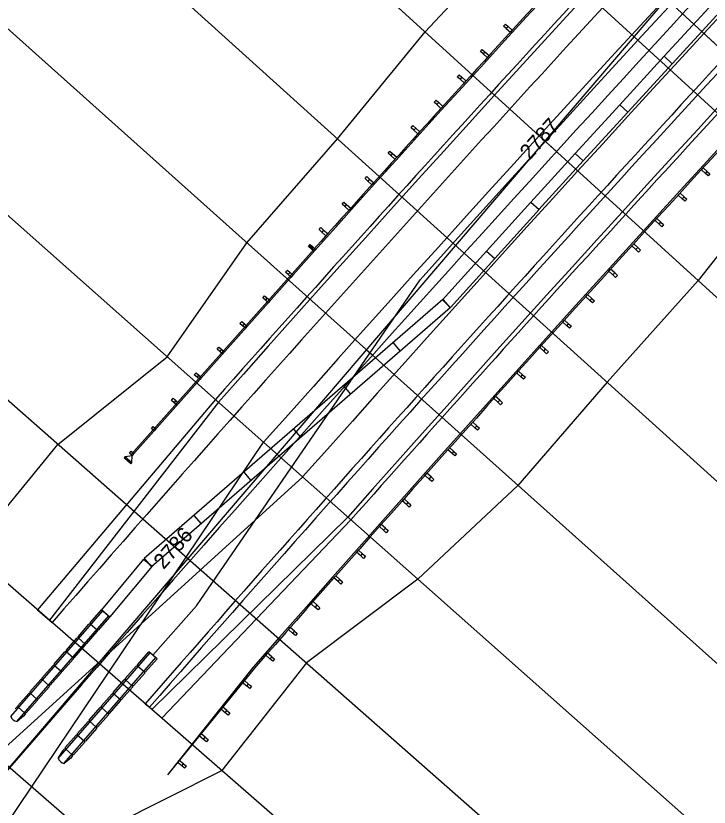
# Model space of a CAD drawing. Extents: x 2376379 to 2383101, y 559608 to 561720.
# Drawn here: x 2376840.8 to 2376967, y 561020.9 to 561165 of the extents above; entities that cross this region are included whole.
import ezdxf

# ---------------------------------------------------------------- set-up
doc = ezdxf.new("R2010")
doc.units = 0
for name, color, linetype in [('BR_X_SV_Bottom_of_Beam', 7, 'Continuous'), ('BR_X_SV_Deck_Top', 7, 'Continuous'), ('DR_X_Headwall', 7, 'Continuous'), ('DT_X_Contour_Minor', 7, 'Continuous'), ('PM_X_CL_Dashed', 7, 'Continuous'), ('PM_X_CL_Pass_Proh_Lt', 7, 'Continuous'), ('PM_X_Surveyed_Line', 7, 'Continuous'), ('PV_X_COP', 7, 'Continuous'), ('PV_X_EOP', 7, 'Continuous'), ('RD_X_Cells', 7, 'Continuous'), ('SV_X_Text', 7, 'Continuous')]:
    doc.layers.add(name, color=color, linetype=linetype)

msp = doc.modelspace()

# ---------------------------------------------------------------- linework, layer by layer
at = {"layer": 'BR_X_SV_Bottom_of_Beam'}
for p, q in [((2376966.95, 561166.42), (2376958.82, 561157.6)), ((2376968.42, 561165.07), (2376960.29, 561156.24)), ((2376958.82, 561157.6), (2376950.71, 561148.75)), ((2376958.82, 561157.6), (2376950.71, 561148.75)), ((2376958.82, 561157.6), (2376950.71, 561148.75)), ((2376958.82, 561157.6), (2376960.29, 561156.24)), ((2376958.82, 561157.6), (2376960.29, 561156.24)), ((2376958.82, 561157.6), (2376960.29, 561156.24)), ((2376958.82, 561157.6), (2376960.29, 561156.24)), ((2376960.29, 561156.24), (2376952.18, 561147.4)), ((2376960.29, 561156.24), (2376952.18, 561147.4)), ((2376960.29, 561156.24), (2376952.18, 561147.4)), ((2376950.71, 561148.75), (2376942.61, 561139.89)), ((2376950.71, 561148.75), (2376952.18, 561147.4)), ((2376950.71, 561148.75), (2376952.18, 561147.4)), ((2376950.71, 561148.75), (2376952.18, 561147.4)), ((2376950.71, 561148.75), (2376952.18, 561147.4)), ((2376952.18, 561147.4), (2376944.09, 561138.54)), ((2376942.61, 561139.89), (2376934.54, 561131.01)), ((2376942.61, 561139.89), (2376944.09, 561138.54)), ((2376942.61, 561139.89), (2376944.09, 561138.54)), ((2376944.09, 561138.54), (2376936.01, 561129.67)), ((2376934.53, 561131.01), (2376926.48, 561122.12)), ((2376934.53, 561131.01), (2376936.02, 561129.67)), ((2376934.54, 561131.01), (2376936.01, 561129.67)), ((2376936.02, 561129.67), (2376927.96, 561120.78)), ((2376926.48, 561122.12), (2376918.44, 561113.21)), ((2376926.48, 561122.12), (2376927.96, 561120.78)), ((2376926.48, 561122.12), (2376927.96, 561120.78)), ((2376927.96, 561120.78), (2376919.92, 561111.87)), ((2376918.52, 561113.29), (2376864.14, 561066.11)), ((2376918.44, 561113.21), (2376919.92, 561111.87)), ((2376918.52, 561113.29), (2376919.83, 561111.78)), ((2376919.83, 561111.78), (2376865.45, 561064.6)), ((2376909.46, 561105.43), (2376910.77, 561103.92)), ((2376900.4, 561097.57), (2376901.71, 561096.06)), ((2376891.33, 561089.7), (2376892.64, 561088.19)), ((2376882.27, 561081.84), (2376883.58, 561080.33)), ((2376781.2, 560979.35), (2376892.99, 561080.98)), ((2376873.2, 561073.98), (2376874.51, 561072.47)), ((2376901.22, 561073.68), (2376865.54, 561038.64)), ((2376864.02, 561066), (2376856.34, 561056.78)), ((2376864.02, 561066), (2376865.56, 561064.72)), ((2376864.14, 561066.11), (2376865.45, 561064.6)), ((2376865.56, 561064.72), (2376857.88, 561055.5)), ((2376854.28, 561054.41), (2376856.36, 561056.79)), ((2376856.34, 561056.78), (2376857.88, 561055.5)), ((2376857.87, 561055.48), (2376856.36, 561056.79)), ((2376839.88, 561037.35), (2376856.61, 561056.58)), ((2376857.61, 561055.7), (2376840.88, 561036.47)), ((2376855.79, 561053.09), (2376857.87, 561055.48)), ((2376852.09, 561051.89), (2376854.06, 561054.15)), ((2376854.29, 561054.17), (2376854.06, 561054.15)), ((2376854.28, 561054.41), (2376854.29, 561054.17)), ((2376855.55, 561053.08), (2376854.29, 561054.17)), ((2376853.6, 561050.58), (2376855.57, 561052.84)), ((2376855.79, 561053.09), (2376855.55, 561053.08)), ((2376855.55, 561053.08), (2376855.57, 561052.84)), ((2376849.9, 561049.38), (2376851.87, 561051.64)), ((2376852.11, 561051.66), (2376851.87, 561051.64)), ((2376852.09, 561051.89), (2376852.11, 561051.66)), ((2376853.36, 561050.56), (2376852.11, 561051.66)), ((2376851.41, 561048.06), (2376853.38, 561050.33)), ((2376853.6, 561050.58), (2376853.36, 561050.56)), ((2376853.36, 561050.56), (2376853.38, 561050.33)), ((2376847.71, 561046.86), (2376849.68, 561049.13)), ((2376849.92, 561049.14), (2376849.68, 561049.13)), ((2376849.9, 561049.38), (2376849.92, 561049.14)), ((2376851.18, 561048.05), (2376849.92, 561049.14)), ((2376851.41, 561048.06), (2376851.18, 561048.05)), ((2376851.18, 561048.05), (2376851.19, 561047.81)), ((2376845.52, 561044.35), (2376847.49, 561046.61)), ((2376847.73, 561046.63), (2376847.49, 561046.61)), ((2376847.71, 561046.86), (2376847.73, 561046.63)), ((2376848.99, 561045.53), (2376847.73, 561046.63)), ((2376849.22, 561045.55), (2376851.19, 561047.81)), ((2376847.03, 561043.04), (2376849, 561045.3)), ((2376849.22, 561045.55), (2376848.99, 561045.53)), ((2376848.99, 561045.53), (2376849, 561045.3)), ((2376843.34, 561041.83), (2376845.31, 561044.1)), ((2376845.54, 561044.11), (2376845.31, 561044.1)), ((2376845.52, 561044.35), (2376845.54, 561044.11)), ((2376846.8, 561043.02), (2376845.54, 561044.11)), ((2376846.81, 561042.78), (2376844.85, 561040.52)), ((2376847.03, 561043.04), (2376846.8, 561043.02)), ((2376846.8, 561043.02), (2376846.81, 561042.78)), ((2376841.15, 561039.32), (2376843.12, 561041.58)), ((2376843.35, 561041.6), (2376843.12, 561041.58)), ((2376843.34, 561041.83), (2376843.35, 561041.6)), ((2376844.61, 561040.5), (2376843.35, 561041.6)), ((2376844.63, 561040.27), (2376842.66, 561038.01)), ((2376844.85, 561040.52), (2376844.61, 561040.5)), ((2376844.61, 561040.5), (2376844.63, 561040.27)), ((2376840.64, 561038.74), (2376840.93, 561039.07)), ((2376841.16, 561039.08), (2376840.93, 561039.07)), ((2376841.15, 561039.32), (2376841.16, 561039.08)), ((2376842.42, 561037.99), (2376841.16, 561039.08)), ((2376842.66, 561038.01), (2376842.42, 561037.99)), ((2376842.42, 561037.99), (2376842.44, 561037.76)), ((2376842.15, 561037.43), (2376840.98, 561036.46)), ((2376842.44, 561037.76), (2376842.15, 561037.43))]:
    msp.add_line(p, q, dxfattribs=at)
for centre, radius, start, end in [((2381174.86, 557281.31), 5724.68, 134.05646, 138.41459), ((2381174.86, 557281.31), 5713.68, 134.05646, 138.41459), ((2376841.14, 561037.78), 1.34, 194.7908, 263.1422)]:
    msp.add_arc(centre, radius, start, end, dxfattribs=at)
at = {"layer": 'BR_X_SV_Deck_Top'}
for p, q in [((2376877.09, 561095.09), (2376844.73, 561056.78)), ((2376844.73, 561056.78), (2376847.37, 561054.48))]:
    msp.add_line(p, q, dxfattribs=at)
for radius, start, end in [(5745.93, 136.826935, 138.414594), (5741.43, 136.827718, 138.914563)]:
    msp.add_arc((2381174.86, 557281.31), radius, start, end, dxfattribs=at)
at = {"layer": 'DR_X_Headwall'}
for p, q in [((2376867.34, 561037.07), (2376901.78, 561073.18)), ((2376865.08, 561039.04), (2376867.34, 561037.07))]:
    msp.add_line(p, q, dxfattribs=at)
msp.add_arc((2381174.86, 557281.31), 5712.93, 137.07842, 138.41459, dxfattribs=at)
at = {"layer": 'DT_X_Contour_Minor'}
msp.add_line((2376855.78, 561016.25), (2376878.27, 561027.54), dxfattribs=at)
for points in [[(2376832.49, 561067.46), (2376848.42, 561086.92), (2376868.33, 561102.87), (2376882.82, 561123.61), (2376899.35, 561142.55), (2376915.28, 561162.04), (2376932.44, 561180.41), (2376951.72, 561196.82), (2376966, 561252.44)], [(2376980.42, 561136.31), (2376965.01, 561116.73), (2376948.44, 561098.22), (2376932.15, 561079.45), (2376913.93, 561062.4), (2376893.67, 561047.12), (2376878.27, 561027.54)]]:
    msp.add_lwpolyline(points, dxfattribs=at)
at = {"layer": 'PM_X_CL_Dashed'}
for p, q in [((2376965.58, 561136.92), (2376965.92, 561137.29)), ((2376966.32, 561136.25), (2376965.58, 561136.92)), ((2376966.66, 561136.61), (2376965.92, 561137.29)), ((2376961.36, 561132.31), (2376961.7, 561132.68)), ((2376962.1, 561131.63), (2376961.36, 561132.31)), ((2376962.44, 561132), (2376961.7, 561132.68)), ((2376957.14, 561127.69), (2376957.48, 561128.06)), ((2376957.88, 561127.01), (2376957.14, 561127.69)), ((2376958.22, 561127.38), (2376957.48, 561128.06)), ((2376952.93, 561123.07), (2376953.27, 561123.44)), ((2376953.67, 561122.39), (2376952.93, 561123.07)), ((2376954.01, 561122.76), (2376953.27, 561123.44)), ((2376948.73, 561118.44), (2376949.06, 561118.81)), ((2376949.8, 561118.14), (2376949.06, 561118.81)), ((2376949.47, 561117.77), (2376948.73, 561118.44)), ((2376944.53, 561113.81), (2376944.87, 561114.18)), ((2376945.27, 561113.14), (2376944.53, 561113.81)), ((2376945.61, 561113.51), (2376944.87, 561114.18)), ((2376940.34, 561109.18), (2376940.67, 561109.55)), ((2376941.08, 561108.51), (2376940.34, 561109.18)), ((2376941.41, 561108.88), (2376940.67, 561109.55)), ((2376936.15, 561104.54), (2376936.48, 561104.91)), ((2376936.89, 561103.87), (2376936.15, 561104.54)), ((2376937.23, 561104.24), (2376936.48, 561104.91)), ((2376931.96, 561099.9), (2376932.3, 561100.27)), ((2376932.71, 561099.23), (2376931.96, 561099.9)), ((2376933.04, 561099.6), (2376932.3, 561100.27)), ((2376927.79, 561095.25), (2376928.12, 561095.62)), ((2376928.86, 561094.95), (2376928.12, 561095.62)), ((2376928.53, 561094.58), (2376927.79, 561095.25)), ((2376923.61, 561090.6), (2376923.95, 561090.97)), ((2376924.36, 561089.93), (2376923.61, 561090.6)), ((2376924.69, 561090.3), (2376923.95, 561090.97)), ((2376919.44, 561085.94), (2376919.78, 561086.31)), ((2376920.19, 561085.27), (2376919.44, 561085.94)), ((2376920.52, 561085.65), (2376919.78, 561086.31)), ((2376915.28, 561081.28), (2376915.61, 561081.65)), ((2376916.03, 561080.61), (2376915.28, 561081.28)), ((2376916.36, 561080.99), (2376915.61, 561081.65)), ((2376911.12, 561076.61), (2376911.46, 561076.99)), ((2376912.2, 561076.32), (2376911.46, 561076.99)), ((2376911.87, 561075.95), (2376911.12, 561076.61)), ((2376906.97, 561071.94), (2376907.3, 561072.32)), ((2376907.72, 561071.28), (2376906.97, 561071.94)), ((2376908.05, 561071.65), (2376907.3, 561072.32)), ((2376902.82, 561067.27), (2376903.16, 561067.64)), ((2376903.57, 561066.6), (2376902.82, 561067.27)), ((2376903.9, 561066.98), (2376903.16, 561067.64)), ((2376898.68, 561062.59), (2376899.01, 561062.96)), ((2376899.43, 561061.93), (2376898.68, 561062.59)), ((2376899.76, 561062.3), (2376899.01, 561062.96)), ((2376894.54, 561057.9), (2376894.87, 561058.28)), ((2376895.62, 561057.62), (2376894.87, 561058.28)), ((2376895.29, 561057.24), (2376894.54, 561057.9)), ((2376890.41, 561053.22), (2376890.74, 561053.59)), ((2376891.16, 561052.55), (2376890.41, 561053.22)), ((2376891.49, 561052.93), (2376890.74, 561053.59)), ((2376886.28, 561048.52), (2376886.61, 561048.9)), ((2376887.04, 561047.86), (2376886.28, 561048.52)), ((2376887.37, 561048.24), (2376886.61, 561048.9)), ((2376883.98, 561046.33), (2376868.4, 561026.76)), ((2376884.19, 561046.14), (2376868.4, 561026.76)), ((2376882.06, 561043.52), (2376882.38, 561043.91)), ((2376883.15, 561043.28), (2376882.38, 561043.91)), ((2376882.83, 561042.89), (2376882.06, 561043.52)), ((2376878.11, 561038.68), (2376878.43, 561039.07)), ((2376878.89, 561038.05), (2376878.11, 561038.68)), ((2376879.2, 561038.44), (2376878.43, 561039.07)), ((2376874.16, 561033.84), (2376874.48, 561034.22)), ((2376874.94, 561033.2), (2376874.16, 561033.84)), ((2376875.25, 561033.59), (2376874.48, 561034.22)), ((2376870.21, 561028.99), (2376870.53, 561029.38)), ((2376871.3, 561028.75), (2376870.53, 561029.38)), ((2376870.99, 561028.36), (2376870.21, 561028.99))]:
    msp.add_line(p, q, dxfattribs=at)
for points in [[(2376967.15, 561136.16), (2376966.81, 561135.8), (2376966.32, 561136.25), (2376966.66, 561136.61)], [(2376962.93, 561131.55), (2376962.59, 561131.18), (2376962.1, 561131.63), (2376962.44, 561132)], [(2376958.71, 561126.93), (2376958.37, 561126.56), (2376957.88, 561127.01), (2376958.22, 561127.38)], [(2376954.5, 561122.31), (2376954.16, 561121.94), (2376953.67, 561122.39), (2376954.01, 561122.76)], [(2376950.3, 561117.69), (2376949.96, 561117.32), (2376949.47, 561117.77), (2376949.8, 561118.14)], [(2376946.1, 561113.06), (2376945.76, 561112.69), (2376945.27, 561113.14), (2376945.61, 561113.51)], [(2376941.91, 561108.43), (2376941.57, 561108.06), (2376941.08, 561108.51), (2376941.41, 561108.88)], [(2376937.72, 561103.8), (2376937.39, 561103.42), (2376936.89, 561103.87), (2376937.23, 561104.24)], [(2376933.54, 561099.15), (2376933.2, 561098.78), (2376932.71, 561099.23), (2376933.04, 561099.6)], [(2376929.36, 561094.51), (2376929.03, 561094.14), (2376928.53, 561094.58), (2376928.86, 561094.95)], [(2376925.19, 561089.86), (2376924.85, 561089.49), (2376924.36, 561089.93), (2376924.69, 561090.3)], [(2376921.02, 561085.2), (2376920.69, 561084.83), (2376920.19, 561085.27), (2376920.52, 561085.65)], [(2376916.86, 561080.54), (2376916.53, 561080.17), (2376916.03, 561080.61), (2376916.36, 561080.99)], [(2376912.7, 561075.88), (2376912.37, 561075.51), (2376911.87, 561075.95), (2376912.2, 561076.32)], [(2376908.55, 561071.21), (2376908.22, 561070.84), (2376907.72, 561071.28), (2376908.05, 561071.65)], [(2376904.4, 561066.54), (2376904.07, 561066.16), (2376903.57, 561066.6), (2376903.9, 561066.98)], [(2376900.26, 561061.86), (2376899.93, 561061.48), (2376899.43, 561061.93), (2376899.76, 561062.3)], [(2376896.12, 561057.18), (2376895.79, 561056.8), (2376895.29, 561057.24), (2376895.62, 561057.62)], [(2376891.99, 561052.49), (2376891.66, 561052.11), (2376891.16, 561052.55), (2376891.49, 561052.93)], [(2376887.87, 561047.8), (2376887.54, 561047.42), (2376887.04, 561047.86), (2376887.37, 561048.24)], [(2376883.67, 561042.86), (2376883.35, 561042.47), (2376882.83, 561042.89), (2376883.15, 561043.28)], [(2376879.72, 561038.01), (2376879.4, 561037.63), (2376878.89, 561038.05), (2376879.2, 561038.44)], [(2376875.77, 561033.17), (2376875.45, 561032.78), (2376874.94, 561033.2), (2376875.25, 561033.59)], [(2376871.82, 561028.33), (2376871.5, 561027.94), (2376870.99, 561028.36), (2376871.3, 561028.75)]]:
    msp.add_lwpolyline(points, close=True, dxfattribs=at)
for centre, radius, start, end in [((2381174.86, 557281.31), 5708.5, 134.05646, 138.73479), ((2381174.92, 557281.26), 5708.3, 136.87154, 138.73476)]:
    msp.add_arc(centre, radius, start, end, dxfattribs=at)
at = {"layer": 'PM_X_CL_Pass_Proh_Lt'}
for p, q in [((2376930.06, 561162.64), (2376930.8, 561161.96)), ((2376930.4, 561163.01), (2376931.14, 561162.33)), ((2376931.14, 561162.33), (2376930.8, 561161.96)), ((2376925.85, 561158.02), (2376926.59, 561157.35)), ((2376926.18, 561158.39), (2376926.92, 561157.72)), ((2376926.92, 561157.72), (2376926.59, 561157.35)), ((2376921.64, 561153.4), (2376922.38, 561152.73)), ((2376921.97, 561153.77), (2376922.71, 561153.1)), ((2376922.71, 561153.1), (2376922.38, 561152.73)), ((2376917.77, 561149.15), (2376918.51, 561148.47)), ((2376917.43, 561148.78), (2376918.17, 561148.1)), ((2376918.51, 561148.47), (2376918.17, 561148.1)), ((2376913.23, 561144.15), (2376913.97, 561143.47)), ((2376913.57, 561144.52), (2376914.31, 561143.84)), ((2376914.31, 561143.84), (2376913.97, 561143.47)), ((2376909.03, 561139.51), (2376909.77, 561138.84)), ((2376909.37, 561139.88), (2376910.11, 561139.21)), ((2376910.11, 561139.21), (2376909.77, 561138.84)), ((2376904.84, 561134.87), (2376905.58, 561134.2)), ((2376905.18, 561135.24), (2376905.92, 561134.57)), ((2376905.92, 561134.57), (2376905.58, 561134.2)), ((2376932.88, 561133.28), (2376932.88, 561133.28)), ((2376900.66, 561130.23), (2376901.4, 561129.56)), ((2376900.99, 561130.6), (2376901.73, 561129.93)), ((2376901.73, 561129.93), (2376901.4, 561129.56)), ((2376896.81, 561125.95), (2376897.55, 561125.29)), ((2376896.48, 561125.58), (2376897.22, 561124.91)), ((2376897.55, 561125.29), (2376897.22, 561124.91)), ((2376895.19, 561122.24), (2376894.2, 561123.13)), ((2376894.36, 561123.31), (2376895.36, 561122.42)), ((2376895.01, 561122.4), (2376861.76, 561085.06)), ((2376895.19, 561122.24), (2376861.94, 561084.9)), ((2376890.21, 561118.64), (2376891.2, 561117.76)), ((2376886.05, 561113.98), (2376887.05, 561113.09)), ((2376881.89, 561109.31), (2376882.89, 561108.42)), ((2376877.74, 561104.64), (2376878.73, 561103.75)), ((2376873.58, 561099.97), (2376874.58, 561099.09)), ((2376869.42, 561095.31), (2376870.42, 561094.42)), ((2376860.64, 561084.68), (2376860.47, 561084.49)), ((2376861.71, 561083.38), (2376860.47, 561084.49)), ((2376861.85, 561083.53), (2376860.6, 561084.64)), ((2376860.64, 561084.68), (2376861.94, 561084.9)), ((2376861.88, 561083.57), (2376860.64, 561084.68)), ((2376861.88, 561083.57), (2376861.94, 561084.9)), ((2376861.88, 561083.57), (2376861.71, 561083.38))]:
    msp.add_line(p, q, dxfattribs=at)
for points in [[(2376929.57, 561163.09), (2376929.91, 561163.46), (2376930.4, 561163.01), (2376930.06, 561162.64)], [(2376925.35, 561158.47), (2376925.69, 561158.84), (2376926.18, 561158.39), (2376925.85, 561158.02)], [(2376921.14, 561153.85), (2376921.48, 561154.22), (2376921.97, 561153.77), (2376921.64, 561153.4)], [(2376916.94, 561149.22), (2376917.27, 561149.59), (2376917.77, 561149.15), (2376917.43, 561148.78)], [(2376912.74, 561144.59), (2376913.07, 561144.96), (2376913.57, 561144.52), (2376913.23, 561144.15)], [(2376908.54, 561139.96), (2376908.87, 561140.33), (2376909.37, 561139.88), (2376909.03, 561139.51)], [(2376904.35, 561135.32), (2376904.68, 561135.69), (2376905.18, 561135.24), (2376904.84, 561134.87)], [(2376900.16, 561130.68), (2376900.5, 561131.05), (2376900.99, 561130.6), (2376900.66, 561130.23)], [(2376895.98, 561126.03), (2376896.31, 561126.4), (2376896.81, 561125.95), (2376896.48, 561125.58)], [(2376894.86, 561122.87), (2376894.53, 561122.5), (2376894.03, 561122.94), (2376894.36, 561123.31)], [(2376895.36, 561122.42), (2376895.03, 561122.05), (2376894.53, 561122.5), (2376894.86, 561122.87)], [(2376890.7, 561118.2), (2376890.37, 561117.83), (2376889.87, 561118.27), (2376890.21, 561118.64)], [(2376891.2, 561117.76), (2376890.87, 561117.38), (2376890.37, 561117.83), (2376890.7, 561118.2)], [(2376886.55, 561113.53), (2376886.22, 561113.16), (2376885.72, 561113.6), (2376886.05, 561113.98)], [(2376887.05, 561113.09), (2376886.72, 561112.72), (2376886.22, 561113.16), (2376886.55, 561113.53)], [(2376882.39, 561108.86), (2376882.06, 561108.49), (2376881.56, 561108.94), (2376881.89, 561109.31)], [(2376882.89, 561108.42), (2376882.56, 561108.05), (2376882.06, 561108.49), (2376882.39, 561108.86)], [(2376878.24, 561104.2), (2376877.9, 561103.82), (2376877.41, 561104.27), (2376877.74, 561104.64)], [(2376878.73, 561103.75), (2376878.4, 561103.38), (2376877.9, 561103.82), (2376878.24, 561104.2)], [(2376874.08, 561099.53), (2376873.75, 561099.16), (2376873.25, 561099.6), (2376873.58, 561099.97)], [(2376874.58, 561099.09), (2376874.25, 561098.71), (2376873.75, 561099.16), (2376874.08, 561099.53)], [(2376869.92, 561094.86), (2376869.59, 561094.49), (2376869.09, 561094.93), (2376869.42, 561095.31)], [(2376870.42, 561094.42), (2376870.09, 561094.05), (2376869.59, 561094.49), (2376869.92, 561094.86)], [(2376866.27, 561089.75), (2376865.93, 561089.38), (2376865.44, 561089.82), (2376865.77, 561090.19)], [(2376862.27, 561085.27), (2376861.94, 561084.9), (2376861.44, 561085.34), (2376861.78, 561085.71)]]:
    msp.add_lwpolyline(points, close=True, dxfattribs=at)
for centre, radius, start, end in [((2381174.86, 557281.31), 5750.5, 134.439365, 138.092558), ((2381174.92, 557281.26), 5750.86, 136.863924, 138.092539)]:
    msp.add_arc(centre, radius, start, end, dxfattribs=at)
at = {"layer": 'PM_X_Surveyed_Line'}
for p, q in [((2376873.95, 561246.65), (2377050.4, 561083.96)), ((2377044.44, 561077.48), (2376867.73, 561239.88)), ((2376850.5, 561221.05), (2377027.91, 561059.42)), ((2377011.47, 561041.29), (2376833.35, 561202.15)), ((2376816.29, 561183.17), (2376995.1, 561023.09)), ((2376978.82, 561004.82), (2376799.3, 561164.12)), ((2376782.41, 561144.99), (2376962.61, 560986.48)), ((2376946.49, 560968.06), (2376765.59, 561125.79)), ((2376748.86, 561106.51), (2376930.44, 560949.58))]:
    msp.add_line(p, q, dxfattribs=at)
at = {"layer": 'PV_X_COP'}
for p, q in [((2376954.74, 561161.29), (2376962.88, 561170.11)), ((2376946.63, 561152.45), (2376954.74, 561161.29)), ((2376938.54, 561143.59), (2376946.63, 561152.45)), ((2376930.46, 561134.71), (2376938.54, 561143.59)), ((2376922.41, 561125.82), (2376930.46, 561134.71)), ((2376914.37, 561116.91), (2376922.41, 561125.82)), ((2376873.63, 561057.54), (2376914.37, 561116.91)), ((2376877.65, 561094.59), (2376846.89, 561054.9)), ((2376812.75, 560978.69), (2376885.88, 561087.29)), ((2376865.72, 561048.51), (2376873.63, 561057.54)), ((2376848.49, 561029.73), (2376865.22, 561048.95)), ((2376866.22, 561048.08), (2376849.49, 561028.85)), ((2376862.89, 561046.78), (2376864.97, 561049.17)), ((2376866.48, 561047.86), (2376864.97, 561049.17)), ((2376860.7, 561044.27), (2376862.67, 561046.53)), ((2376862.9, 561046.55), (2376862.67, 561046.53)), ((2376862.89, 561046.78), (2376862.9, 561046.55)), ((2376864.16, 561045.45), (2376862.9, 561046.55)), ((2376864.4, 561045.47), (2376866.48, 561047.86)), ((2376862.21, 561042.96), (2376864.18, 561045.22)), ((2376864.4, 561045.47), (2376864.16, 561045.45)), ((2376864.16, 561045.45), (2376864.18, 561045.22)), ((2376858.51, 561041.75), (2376860.48, 561044.02)), ((2376860.72, 561044.03), (2376860.48, 561044.02)), ((2376860.7, 561044.27), (2376860.72, 561044.03)), ((2376861.97, 561042.94), (2376860.72, 561044.03)), ((2376860.02, 561040.44), (2376861.99, 561042.7)), ((2376862.21, 561042.96), (2376861.97, 561042.94)), ((2376861.97, 561042.94), (2376861.99, 561042.7)), ((2376856.32, 561039.24), (2376858.29, 561041.5)), ((2376858.53, 561041.52), (2376858.29, 561041.5)), ((2376858.51, 561041.75), (2376858.53, 561041.52)), ((2376859.79, 561040.42), (2376858.53, 561041.52)), ((2376857.83, 561037.93), (2376859.8, 561040.19)), ((2376860.02, 561040.44), (2376859.79, 561040.42)), ((2376859.79, 561040.42), (2376859.8, 561040.19)), ((2376854.14, 561036.72), (2376856.1, 561038.99)), ((2376856.34, 561039), (2376856.1, 561038.99)), ((2376856.32, 561039.24), (2376856.34, 561039)), ((2376857.6, 561037.91), (2376856.34, 561039)), ((2376857.83, 561037.93), (2376857.6, 561037.91)), ((2376857.6, 561037.91), (2376857.61, 561037.67)), ((2376851.95, 561034.21), (2376853.92, 561036.47)), ((2376854.15, 561036.49), (2376853.92, 561036.47)), ((2376854.14, 561036.72), (2376854.15, 561036.49)), ((2376855.41, 561035.4), (2376854.15, 561036.49)), ((2376855.64, 561035.41), (2376857.61, 561037.67)), ((2376855.43, 561035.16), (2376853.46, 561032.9)), ((2376855.64, 561035.41), (2376855.41, 561035.4)), ((2376855.41, 561035.4), (2376855.43, 561035.16)), ((2376849.76, 561031.7), (2376851.73, 561033.96)), ((2376851.96, 561033.98), (2376851.73, 561033.96)), ((2376851.95, 561034.21), (2376851.96, 561033.98)), ((2376853.22, 561032.88), (2376851.96, 561033.98)), ((2376853.24, 561032.65), (2376851.27, 561030.38)), ((2376853.46, 561032.9), (2376853.22, 561032.88)), ((2376853.22, 561032.88), (2376853.24, 561032.65)), ((2376849.25, 561031.12), (2376848.46, 561029.82)), ((2376849.25, 561031.12), (2376849.54, 561031.44)), ((2376849.78, 561031.46), (2376849.54, 561031.44)), ((2376849.76, 561031.7), (2376849.78, 561031.46)), ((2376851.03, 561030.37), (2376849.78, 561031.46)), ((2376850.76, 561029.8), (2376849.59, 561028.83)), ((2376851.05, 561030.13), (2376850.76, 561029.8)), ((2376851.27, 561030.38), (2376851.03, 561030.37)), ((2376851.03, 561030.37), (2376851.05, 561030.13))]:
    msp.add_line(p, q, dxfattribs=at)
for centre, radius, start, end in [((2381174.86, 557281.31), 5745.18, 134.056462, 138.414594), ((2381174.86, 557281.31), 5734.18, 134.056462, 138.414594), ((2376849.75, 561030.16), 1.34, 194.7917, 263.1431)]:
    msp.add_arc(centre, radius, start, end, dxfattribs=at)
at = {"layer": 'PV_X_EOP'}
for p, q in [((2376939.21, 561140.24), (2376937.73, 561141.59)), ((2376905.69, 561103.13), (2376904.8, 561103.93)), ((2376872.51, 561065.73), (2376871.01, 561067.05))]:
    msp.add_line(p, q, dxfattribs=at)
at = {"layer": 'RD_X_Cells'}
msp.add_line((2376415.94, 560532.55), (2376995.66, 561210.67), dxfattribs=at)
msp.add_arc((2381174.86, 557281.31), 5729.93, 134.056462, 139.473129, dxfattribs=at)
msp.add_arc((2381174.86, 557281.31), 5729.93, 134.056462, 139.473129, dxfattribs=at)
at = {"layer": 'SV_X_Text'}
for p, q in [((2376970.27, 561157.85), (2376953.36, 561173.44)), ((2376864.33, 561039.7), (2376865.08, 561039.04))]:
    msp.add_line(p, q, dxfattribs=at)
for radius, start in [(5717.93, 137.07471), (5718.93, 137.32466)]:
    msp.add_arc((2381174.86, 557281.31), radius, start, 138.91456, dxfattribs=at)

# ---------------------------------------------------------------- texts
at = {"layer": 'PV_X_EOP'}
for s, rotation, p in [('2787', 47.6646, (2376934.31, 561138.57)), ('2786', 48.6646, (2376867.67, 561064.02))]:
    msp.add_text(s, height=2.8, rotation=rotation, dxfattribs=at).set_placement(p)

doc.saveas('drawing.dxf')
